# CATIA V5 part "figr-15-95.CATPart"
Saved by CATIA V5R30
Part number: Part1
Bounding box of the stored display mesh (mm): x -40 to 40, y -60 to 60, z -4 to 2
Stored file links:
  D:\PROJECTS\CATIA V56R 2020\Resources\Parts File\c15_catia_v5_6r2020_prt\figr-15-95.CATPart
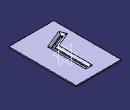
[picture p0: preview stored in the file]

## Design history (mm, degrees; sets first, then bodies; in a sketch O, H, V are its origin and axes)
SheetMetalParameters1: Thickness 2, BendRadius 4, KFactor 0.400515 {= log(min(100,max(20*SheetMetalParameters1.BendRadius,SheetMetalParameters1.Thickness)/SheetMetalParameters1.Thickness))/log(100)/2}, ReliefRadialLength 1, ReliefAxialLength 2, MinimumBendRadius 0
Body1 (main body)
  Sketch1 on xy-plane, origin (0, 0, 0), H (-1, 0, 0), V (0, -1, 0)
    line L1 (40, 60) -> (40, -60)
    line L2 (40, -60) -> (-40, -60)
    line L3 (-40, -60) -> (-40, 60)
    line L4 (-40, 60) -> (40, 60)
    length L4 = 80
    length L1 = 120
    vertical: L1 V, L3 V
    horizontal: L2 H, L4 H
    equidistance: L1 L3 O, L2 L4 O
  Wall1: Thickness 2, Profile Sketch1, OffsetValue 0
  Sketch2 on face of Wall1, origin (0, 0, 2), H (1, 0, 0), V (0, 1, 0)
    line L1 (0, 40.0798) -> (0, -21.0085)
    line L2 (0, -21.0085) -> (-27, -32)
    vertical: L1 V
  d_Stamp1: NewRoot_AttribNormalisation "No Standard", Stamp_FilletRadius 2, Stamp_IntersectFilletRadius 2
